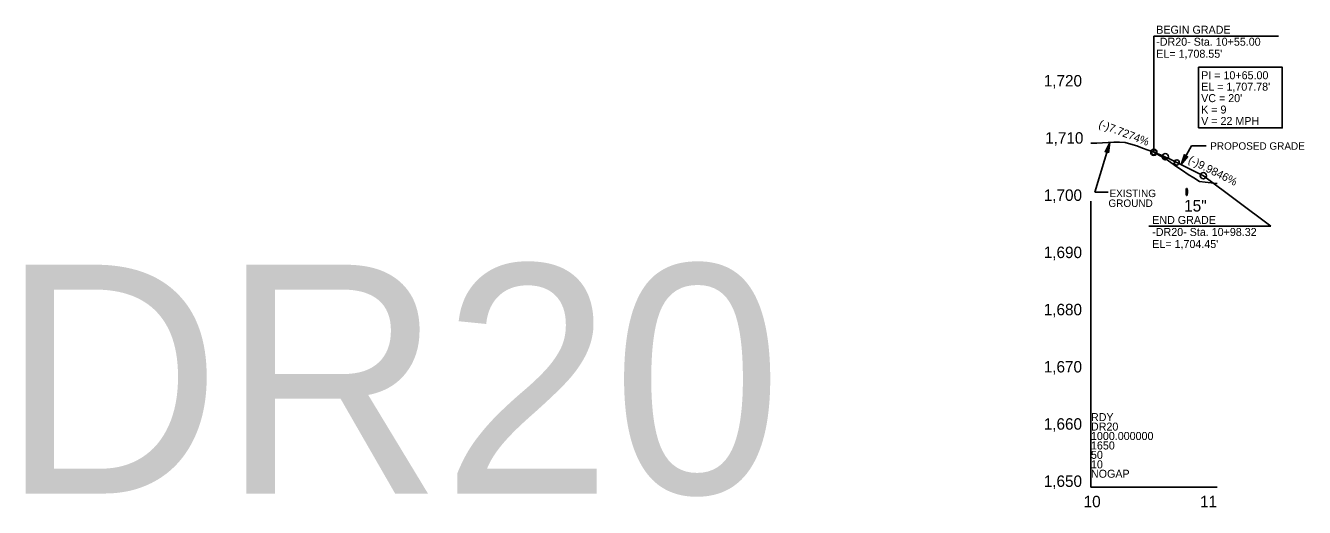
# Model space of a CAD drawing. Extents: x 498575 to 532350, y 405181 to 484585.
# Drawn here: x 526352 to 527471, y 434251 to 434672 of the extents above; entities that cross this region are included whole.
import ezdxf

# ---------------------------------------------------------------- set-up
doc = ezdxf.new("R2010")
doc.units = 0
for name, color, linetype in [('Exist Profile Cell', 7, 'Continuous'), ('Exist Vertical Profile Ground Line', 7, 'Continuous'), ('Exist Vertical Profile Horizontal Axis Label Major', 7, 'Continuous'), ('Exist Vertical Profile Vertical Axis Label', 7, 'Continuous'), ('Prop Drainage Structure Pipe Welded Steel 54in Label', 7, 'Continuous'), ('Prop Grid Mask', 7, 'Continuous'), ('Prop PFL Text', 7, 'Continuous'), ('Prop Vertical Profile Curve Label', 7, 'Continuous'), ('Prop Vertical Profile Grade', 7, 'Continuous'), ('Prop Vertical Profile Grade Label', 7, 'Continuous'), ('Prop VPI Label', 7, 'Continuous'), ('Scratch_Level_7', 7, 'Continuous')]:
    doc.layers.add(name, color=color, linetype=linetype)

msp = doc.modelspace()

# ---------------------------------------------------------------- linework, layer by layer
at = {"layer": 'Exist Profile Cell'}
for q in [(527283.8, 434518.3), (527394.1, 434268.3), (527283.8, 434268.3)]:
    msp.add_line((527283.8, 434268.3), q, dxfattribs=at)
at = {"layer": 'Exist Vertical Profile Ground Line'}
msp.add_lwpolyline([(527283.8, 434568.9), (527288.8, 434569), (527293.8, 434569.2), (527298.8, 434569.5), (527303.8, 434569.9), (527308.8, 434569.8), (527313.8, 434569.7), (527318.8, 434568.3), (527323.8, 434566.7), (527328.8, 434564.7), (527333.8, 434562.9), (527338.8, 434561.1), (527343.8, 434558.3), (527348.8, 434555.5), (527353.8, 434552), (527358.8, 434548.3), (527363.8, 434545.1), (527368.8, 434541.7), (527373.8, 434538.6), (527378.8, 434535.5), (527383.8, 434534.9), (527388.8, 434534.3), (527393.8, 434533.7), (527394.1, 434533.7)], dxfattribs=at)
at = {"layer": 'Prop Drainage Structure Pipe Welded Steel 54in Label'}
msp.add_ellipse((527367.6, 434526.4), major_axis=(0, 3.12), ratio=0.2, dxfattribs=at)
at = {"layer": 'Prop Grid Mask'}
msp.add_lwpolyline([(527378, 434582.3), (527451.1, 434582.3), (527451.1, 434635.4), (527378, 434635.4)], close=True, dxfattribs=at)
at = {"layer": 'Prop PFL Text'}
for p, q in [((527300.4, 434569.7), (527287.2, 434526.3)), ((527371.7, 434566.7), (527362.7, 434550.3)), ((527371.7, 434566.7), (527384.6, 434566.7)), ((527287.2, 434526.3), (527298.9, 434526.3))]:
    msp.add_line(p, q, dxfattribs=at)
for points in [[(527299.2, 434560.6), (527300.4, 434569.7), (527296.1, 434561.5), (527298, 434562.1)], [(527368.4, 434557.4), (527362.7, 434550.3), (527365.7, 434559), (527366.5, 434557.2)]]:
    msp.add_lwpolyline(points, close=True, dxfattribs=at)
at = {"layer": 'Prop Vertical Profile Curve Label'}
for centre in [(527338.8, 434561.1), (527358.8, 434552.2)]:
    msp.add_circle(centre, 2.25, dxfattribs=at)
at = {"layer": 'Prop Vertical Profile Grade'}
msp.add_line((527358.8, 434552.2), (527382.1, 434540.6), dxfattribs=at)
msp.add_spline([(527338.8, 434561.1), (527339.2, 434560.9), (527339.6, 434560.8), (527340, 434560.6), (527340.4, 434560.5), (527340.8, 434560.3), (527341.2, 434560.1), (527341.6, 434560), (527342, 434559.8), (527342.4, 434559.7), (527342.8, 434559.5), (527343.2, 434559.3), (527343.6, 434559.2), (527344, 434559), (527344.4, 434558.8), (527344.8, 434558.7), (527345.2, 434558.5), (527345.6, 434558.3), (527346, 434558.2), (527346.4, 434558), (527346.8, 434557.8), (527347.2, 434557.6), (527347.6, 434557.5), (527348, 434557.3), (527348.4, 434557.1), (527348.8, 434556.9), (527349.2, 434556.8), (527349.6, 434556.6), (527350, 434556.4), (527350.4, 434556.2), (527350.8, 434556), (527351.2, 434555.9), (527351.6, 434555.7), (527352, 434555.5), (527352.4, 434555.3), (527352.8, 434555.1), (527353.2, 434554.9), (527353.6, 434554.7), (527354, 434554.6), (527354.4, 434554.4), (527354.8, 434554.2), (527355.2, 434554), (527355.6, 434553.8), (527356, 434553.6), (527356.4, 434553.4), (527356.8, 434553.2), (527357.2, 434553), (527357.6, 434552.8), (527358, 434552.6), (527358.4, 434552.4), (527358.8, 434552.2)], degree=3, dxfattribs=at)
at = {"layer": 'Prop VPI Label'}
for p, q in [((527338.8, 434662.7), (527447.9, 434662.7)), ((527338.8, 434561.1), (527338.8, 434662.7)), ((527338.8, 434561.1), (527346.2, 434558.2)), ((527358.8, 434552.2), (527351.3, 434556)), ((527441.1, 434496.5), (527382.1, 434540.6)), ((527334.5, 434496.5), (527441.1, 434496.5))]:
    msp.add_line(p, q, dxfattribs=at)
for centre in [(527338.8, 434561.1), (527348.8, 434557.2), (527382.1, 434540.6)]:
    msp.add_circle(centre, 2.75, dxfattribs=at)

# ---------------------------------------------------------------- texts
at = {"layer": 'Exist Profile Cell'}
for s, p in [('RDY', (527283.8, 434326.1)), ('1000.000000', (527283.8, 434309.6)), ('DR20', (527283.8, 434317.8)), ('1650', (527283.8, 434301.3)), ('50', (527283.8, 434293.1)), ('10', (527283.8, 434284.8)), ('NOGAP', (527283.8, 434276.6))]:
    msp.add_text(s, height=7, dxfattribs=at).set_placement(p)
at = {"layer": 'Exist Vertical Profile Horizontal Axis Label Major'}
for s, p in [('10', (527277.4, 434250.8)), ('11', (527379.2, 434250.8))]:
    msp.add_text(s, height=10, dxfattribs=at).set_placement(p)
at = {"layer": 'Exist Vertical Profile Vertical Axis Label'}
for s, p in [('1,720', (527242.5, 434618.6)), ('1,710', (527243.7, 434568.6)), ('1,700', (527242.5, 434518.6)), ('1,690', (527242.5, 434468.6)), ('1,680', (527242.5, 434418.6)), ('1,670', (527242.5, 434368.6)), ('1,660', (527242.5, 434318.6)), ('1,650', (527242.5, 434268.6))]:
    msp.add_text(s, height=10, dxfattribs=at).set_placement(p)
at = {"layer": 'Prop Drainage Structure Pipe Welded Steel 54in Label'}
msp.add_text('15"', height=10.12, dxfattribs=at).set_placement((527365.2, 434509.3))
at = {"layer": 'Prop PFL Text'}
for s, height, p in [('PROPOSED GRADE', 6.516, (527388.1, 434563.3)), ('EXISTING ', 6.52, (527300, 434521.9)), ('GROUND', 6.52, (527299.1, 434513.3))]:
    msp.add_text(s, height=height, dxfattribs=at).set_placement(p)
at = {"layer": 'Prop Vertical Profile Curve Label'}
msp.add_text('V = 22 MPH ', height=7, dxfattribs=at).set_placement((527380.2, 434584.9))
at = {"layer": 'Prop Vertical Profile Grade Label'}
for s, rotation, p in [('(-)7.7274%', 338.875, (527289.9, 434583.2)), ('(-)9.9846%', 333.4703, (527368.2, 434552.2))]:
    msp.add_text(s, height=7, rotation=rotation, dxfattribs=at).set_placement(p)
at = {"layer": 'Prop VPI Label'}
for s, p in [('BEGIN GRADE', (527340.9, 434664.7)), ('-DR20- Sta. 10+55.00', (527340.9, 434654.2)), ("EL= 1,708.55'", (527340.9, 434643.7)), ('PI = 10+65.00', (527380.2, 434624.9)), ("EL = 1,707.78'", (527380.2, 434614.9)), ("VC = 20'", (527380.2, 434604.9)), ('K = 9', (527380.2, 434594.9)), ('END GRADE', (527337.4, 434498.4)), ('-DR20- Sta. 10+98.32', (527337.4, 434487.9)), ("EL= 1,704.45'", (527337.4, 434477.4))]:
    msp.add_text(s, height=7, dxfattribs=at).set_placement(p)
at = {"layer": 'Scratch_Level_7'}
msp.add_text('DR20', height=200, dxfattribs=at).set_placement((526329.9, 434262.8))

doc.saveas('drawing.dxf')
